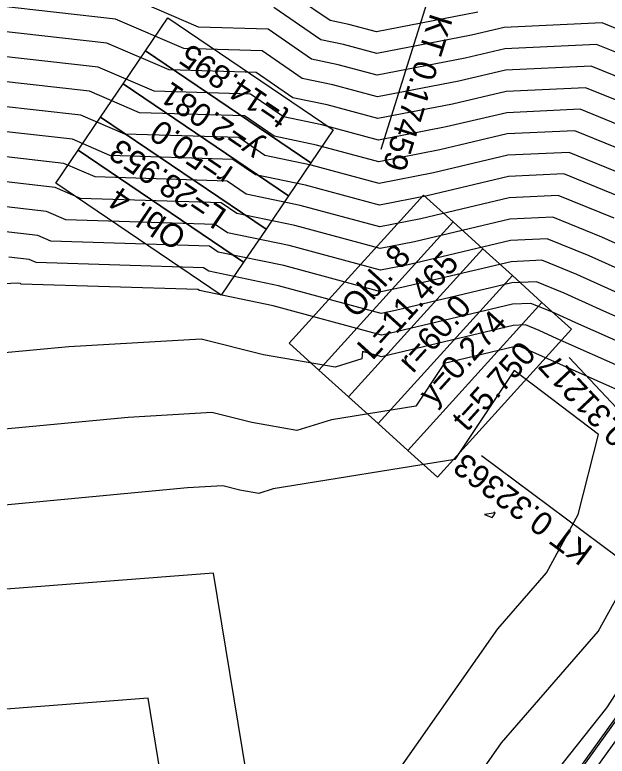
# Model space of a CAD drawing. Extents: x -549394 to -546608, y -1037055 to -1033629.
# Drawn here: x -547053.3 to -546964.3, y -1036015.8 to -1035904.5 of the extents above; entities that cross this region are included whole.
import ezdxf

# ---------------------------------------------------------------- set-up
doc = ezdxf.new("R2010")
doc.units = 0
for name, color, linetype in [('hlavni_vrst', 7, 'Continuous'), ('norm_vrst', 7, 'Continuous'), ('x_navrh_C31', 7, 'Continuous'), ('x_osa_C31', 7, 'Continuous'), ('x_popis_oblouky_C31', 7, 'Continuous')]:
    doc.layers.add(name, color=color, linetype=linetype)

msp = doc.modelspace()

# ---------------------------------------------------------------- linework, layer by layer
at = {"layer": 'hlavni_vrst'}
for p, q in [((-547007.32, -1035908.26), (-547014.4, -1035903.41)), ((-546965.11, -1035905.72), (-546979.83, -1035906.4)), ((-546948.31, -1035912.56), (-546965.11, -1035905.72)), ((-546979.83, -1035906.4), (-546984.72, -1035907.55)), ((-547003.92, -1035908.97), (-547007.32, -1035908.26)), ((-546984.72, -1035907.55), (-546998.92, -1035910.32)), ((-546998.92, -1035910.32), (-547003.92, -1035908.97)), ((-547042.05, -1035915.97), (-547063.4, -1035913.56)), ((-547034.56, -1035919.2), (-547042.05, -1035915.97)), ((-547018.79, -1035919.68), (-547034.56, -1035919.2)), ((-547014.34, -1035922.74), (-547018.79, -1035919.68)), ((-547007.99, -1035924.06), (-547014.34, -1035922.74)), ((-546979.34, -1035922.38), (-546989.48, -1035924.79)), ((-546969.22, -1035921.92), (-546979.34, -1035922.38)), ((-546957.68, -1035926.62), (-546969.22, -1035921.92)), ((-546998.65, -1035926.57), (-547007.99, -1035924.06)), ((-546989.48, -1035924.79), (-546998.65, -1035926.57)), ((-547048.55, -1035934.02), (-547056.82, -1035933.09)), ((-547045.65, -1035935.27), (-547048.55, -1035934.02)), ((-547023.18, -1035935.96), (-547045.65, -1035935.27)), ((-547021.36, -1035937.21), (-547023.18, -1035935.96)), ((-547012.07, -1035939.14), (-547021.36, -1035937.21)), ((-546978.84, -1035938.37), (-546994.24, -1035942.02)), ((-546973.33, -1035938.11), (-546978.84, -1035938.37)), ((-546967.05, -1035940.68), (-546973.33, -1035938.11)), ((-546998.39, -1035942.82), (-547012.07, -1035939.14)), ((-546958.93, -1035944.34), (-546967.05, -1035940.68)), ((-546994.24, -1035942.02), (-546998.39, -1035942.82)), ((-546978.35, -1035954.36), (-546988.8, -1035956.83)), ((-546977.44, -1035954.31), (-546978.35, -1035954.36)), ((-546976.41, -1035954.73), (-546977.44, -1035954.31)), ((-546975.08, -1035955.33), (-546976.41, -1035954.73)), ((-546959.74, -1035962.17), (-546975.08, -1035955.33)), ((-546988.8, -1035956.83), (-546993.09, -1035963.24)), ((-546993.09, -1035963.24), (-547005.75, -1035965.29)), ((-547036.25, -1035964.94), (-547063.11, -1035967.47)), ((-547023.68, -1035964.21), (-547036.25, -1035964.94)), ((-547017.72, -1035965.72), (-547023.68, -1035964.21)), ((-547010.93, -1035966.89), (-547017.72, -1035965.72)), ((-547005.75, -1035965.29), (-547010.93, -1035966.89)), ((-546965.68, -1035997.09), (-546956.18, -1035979.65)), ((-546980.23, -1036013.78), (-546965.68, -1035997.09)), ((-546988.48, -1036025.58), (-546980.23, -1036013.78))]:
    msp.add_line(p, q, dxfattribs=at)
at = {"layer": 'norm_vrst'}
for p, q in [((-547005.92, -1035905.37), (-547013.52, -1035900.15)), ((-547025.69, -1035906.34), (-547036.85, -1035901.52)), ((-547038.15, -1035905.14), (-547067.34, -1035901.85)), ((-546983.77, -1035904.11), (-546998.97, -1035907.07)), ((-547039.45, -1035908.75), (-547066.03, -1035905.75)), ((-547027.91, -1035909.55), (-547038.15, -1035905.14)), ((-547003.11, -1035905.95), (-547005.92, -1035905.37)), ((-546998.97, -1035907.07), (-547003.11, -1035905.95)), ((-547015.27, -1035906.66), (-547025.69, -1035906.34)), ((-547008.73, -1035911.16), (-547015.27, -1035906.66)), ((-547030.13, -1035912.77), (-547039.45, -1035908.75)), ((-546965.94, -1035908.96), (-546979.73, -1035909.59)), ((-546950.18, -1035915.37), (-546965.94, -1035908.96)), ((-547040.75, -1035912.36), (-547064.71, -1035909.66)), ((-547016.15, -1035909.92), (-547027.91, -1035909.55)), ((-547010.13, -1035914.05), (-547016.15, -1035909.92)), ((-546979.73, -1035909.59), (-546985.67, -1035911)), ((-547004.74, -1035911.99), (-547008.73, -1035911.16)), ((-546985.67, -1035911), (-546998.86, -1035913.57)), ((-547032.35, -1035915.98), (-547040.75, -1035912.36)), ((-547017.03, -1035913.17), (-547030.13, -1035912.77)), ((-546998.86, -1035913.57), (-547004.74, -1035911.99)), ((-546979.63, -1035912.79), (-546986.62, -1035914.45)), ((-546966.76, -1035912.2), (-546979.63, -1035912.79)), ((-546952.06, -1035918.19), (-546966.76, -1035912.2)), ((-547011.53, -1035916.95), (-547017.03, -1035913.17)), ((-547005.55, -1035915), (-547010.13, -1035914.05)), ((-546998.81, -1035916.82), (-547005.55, -1035915)), ((-546986.62, -1035914.45), (-546998.81, -1035916.82)), ((-547017.91, -1035916.43), (-547032.35, -1035915.98)), ((-546979.53, -1035915.99), (-546987.57, -1035917.89)), ((-546967.58, -1035915.44), (-546979.53, -1035915.99)), ((-546953.93, -1035921), (-546967.58, -1035915.44)), ((-547012.94, -1035919.84), (-547017.91, -1035916.43)), ((-547006.37, -1035918.02), (-547011.53, -1035916.95)), ((-547043.35, -1035919.58), (-547062.08, -1035917.47)), ((-546998.76, -1035920.07), (-547006.37, -1035918.02)), ((-546987.57, -1035917.89), (-546998.76, -1035920.07)), ((-546979.43, -1035919.19), (-546988.53, -1035921.34)), ((-546968.4, -1035918.68), (-546979.43, -1035919.19)), ((-546955.8, -1035923.81), (-546968.4, -1035918.68)), ((-547036.78, -1035922.41), (-547043.35, -1035919.58)), ((-547007.18, -1035921.04), (-547012.94, -1035919.84)), ((-547044.65, -1035923.19), (-547060.76, -1035921.37)), ((-546998.7, -1035923.32), (-547007.18, -1035921.04)), ((-546988.53, -1035921.34), (-546998.7, -1035923.32)), ((-547019.67, -1035922.94), (-547036.78, -1035922.41)), ((-547039, -1035925.63), (-547044.65, -1035923.19)), ((-547015.75, -1035925.63), (-547019.67, -1035922.94)), ((-547045.95, -1035926.8), (-547059.45, -1035925.28)), ((-547020.55, -1035926.2), (-547039, -1035925.63)), ((-547017.15, -1035928.53), (-547020.55, -1035926.2)), ((-547008.81, -1035927.07), (-547015.75, -1035925.63)), ((-546979.24, -1035925.58), (-546990.43, -1035928.23)), ((-546970.05, -1035925.16), (-546979.24, -1035925.58)), ((-546959.55, -1035929.43), (-546970.05, -1035925.16)), ((-547041.22, -1035928.84), (-547045.95, -1035926.8)), ((-546998.6, -1035929.82), (-547008.81, -1035927.07)), ((-546990.43, -1035928.23), (-546998.6, -1035929.82)), ((-546970.87, -1035928.39), (-546979.14, -1035928.78)), ((-546961.42, -1035932.24), (-546970.87, -1035928.39)), ((-547047.25, -1035930.41), (-547058.13, -1035929.18)), ((-547021.42, -1035929.45), (-547041.22, -1035928.84)), ((-547018.55, -1035931.42), (-547021.42, -1035929.45)), ((-547009.62, -1035930.09), (-547017.15, -1035928.53)), ((-546979.14, -1035928.78), (-546991.38, -1035931.68)), ((-547043.43, -1035932.06), (-547047.25, -1035930.41)), ((-546998.55, -1035933.07), (-547009.62, -1035930.09)), ((-547010.44, -1035933.11), (-547018.55, -1035931.42)), ((-546991.38, -1035931.68), (-546998.55, -1035933.07)), ((-546971.69, -1035931.63), (-546979.04, -1035931.98)), ((-546963.3, -1035935.05), (-546971.69, -1035931.63)), ((-547022.3, -1035932.71), (-547043.43, -1035932.06)), ((-547019.96, -1035934.32), (-547022.3, -1035932.71)), ((-546979.04, -1035931.98), (-546992.33, -1035935.12)), ((-546998.49, -1035936.32), (-547010.44, -1035933.11)), ((-547011.25, -1035936.12), (-547019.96, -1035934.32)), ((-546972.51, -1035934.87), (-546978.94, -1035935.17)), ((-546965.17, -1035937.87), (-546972.51, -1035934.87)), ((-546998.44, -1035939.57), (-547011.25, -1035936.12)), ((-546992.33, -1035935.12), (-546998.49, -1035936.32)), ((-546978.94, -1035935.17), (-546993.29, -1035938.57)), ((-547049.85, -1035937.63), (-547055.5, -1035936.99)), ((-547047.87, -1035938.49), (-547049.85, -1035937.63)), ((-546955.7, -1035942.14), (-546965.17, -1035937.87)), ((-547024.06, -1035939.22), (-547047.87, -1035938.49)), ((-547022.77, -1035940.11), (-547024.06, -1035939.22)), ((-546993.29, -1035938.57), (-546998.44, -1035939.57)), ((-547012.88, -1035942.16), (-547022.77, -1035940.11)), ((-547051.15, -1035941.24), (-547054.19, -1035940.9)), ((-547050.09, -1035941.7), (-547051.15, -1035941.24)), ((-547024.94, -1035942.48), (-547050.09, -1035941.7)), ((-546978.74, -1035941.57), (-546995.19, -1035945.46)), ((-546974.16, -1035941.35), (-546978.74, -1035941.57)), ((-546968.92, -1035943.49), (-546974.16, -1035941.35)), ((-547024.17, -1035943), (-547024.94, -1035942.48)), ((-546998.34, -1035946.08), (-547012.88, -1035942.16)), ((-547013.7, -1035945.18), (-547024.17, -1035943)), ((-546962.16, -1035946.54), (-546968.92, -1035943.49)), ((-547052.87, -1035944.81), (-547081.68, -1035946.16)), ((-547052.45, -1035944.85), (-547052.87, -1035944.81)), ((-547052.31, -1035944.92), (-547052.45, -1035944.85)), ((-547025.82, -1035945.73), (-547052.31, -1035944.92)), ((-546978.64, -1035944.76), (-546996.14, -1035948.91)), ((-546974.98, -1035944.59), (-546978.64, -1035944.76)), ((-546970.79, -1035946.3), (-546974.98, -1035944.59)), ((-547025.57, -1035945.9), (-547025.82, -1035945.73)), ((-547014.51, -1035948.19), (-547025.57, -1035945.9)), ((-546998.28, -1035949.33), (-547013.7, -1035945.18)), ((-546995.19, -1035945.46), (-546998.34, -1035946.08)), ((-546965.39, -1035948.74), (-546970.79, -1035946.3)), ((-546998.23, -1035952.58), (-547014.51, -1035948.19)), ((-546978.54, -1035947.96), (-546997.09, -1035952.36)), ((-546975.8, -1035947.83), (-546978.54, -1035947.96)), ((-546972.67, -1035949.11), (-546975.8, -1035947.83)), ((-546996.14, -1035948.91), (-546998.28, -1035949.33)), ((-546968.62, -1035950.94), (-546972.67, -1035949.11)), ((-546953.81, -1035953.9), (-546965.39, -1035948.74)), ((-546978.45, -1035951.16), (-546998.05, -1035955.8)), ((-546976.62, -1035951.07), (-546978.45, -1035951.16)), ((-546974.54, -1035951.92), (-546976.62, -1035951.07)), ((-546955.79, -1035956.66), (-546968.62, -1035950.94)), ((-546997.09, -1035952.36), (-546998.23, -1035952.58)), ((-546971.85, -1035953.14), (-546974.54, -1035951.92)), ((-547025.33, -1035953.18), (-547045.17, -1035954.34)), ((-547015.93, -1035955.56), (-547025.33, -1035953.18)), ((-546957.77, -1035959.42), (-546971.85, -1035953.14)), ((-547045.17, -1035954.34), (-547057.43, -1035955.49)), ((-547001.1, -1035955.04), (-547001.17, -1035956.17)), ((-546998.18, -1035955.83), (-547001.1, -1035955.04)), ((-547005.2, -1035957.42), (-547015.93, -1035955.56)), ((-547001.17, -1035956.17), (-547005.2, -1035957.42)), ((-546998.05, -1035955.8), (-546998.18, -1035955.83)), ((-546978.31, -1035957.92), (-546987.24, -1035971.27)), ((-546965.65, -1035967.53), (-546978.31, -1035957.92)), ((-546968.7, -1035979.52), (-546965.65, -1035967.53)), ((-546987.24, -1035971.27), (-547014.47, -1035975.69)), ((-547027.34, -1035975.54), (-547068.8, -1035979.44)), ((-547022.03, -1035975.23), (-547027.34, -1035975.54)), ((-547019.52, -1035975.87), (-547022.03, -1035975.23)), ((-547016.65, -1035976.36), (-547019.52, -1035975.87)), ((-547014.47, -1035975.69), (-547016.65, -1035976.36)), ((-546981.4, -1035979.3), (-546982.75, -1035979.52)), ((-546982.75, -1035979.52), (-546981.61, -1035979.95)), ((-546981.61, -1035979.95), (-546981.33, -1035979.55)), ((-546981.31, -1035979.17), (-546981.4, -1035979.3)), ((-546981.33, -1035979.55), (-546981.26, -1035979.47)), ((-546981.18, -1035979.26), (-546981.31, -1035979.17)), ((-546981.26, -1035979.47), (-546981.21, -1035979.38)), ((-546981.21, -1035979.38), (-546981.18, -1035979.26)), ((-546973.47, -1035988.28), (-546968.7, -1035979.52)), ((-547023.47, -1035988.34), (-547072.1, -1035992.07)), ((-547016.71, -1036029.45), (-547023.47, -1035988.34)), ((-546980.78, -1035996.67), (-546973.47, -1035988.28)), ((-547003.52, -1036029.16), (-546980.78, -1035996.67)), ((-546964.39, -1036008.54), (-546961.24, -1036003.64)), ((-547033.27, -1036007.09), (-547059.49, -1036009.1)), ((-547029.62, -1036029.26), (-547033.27, -1036007.09)), ((-546972.34, -1036018.53), (-546964.39, -1036008.54))]:
    msp.add_line(p, q, dxfattribs=at)
at = {"layer": 'x_navrh_C31'}
msp.add_line((-547002.86, -1036065.86), (-546951.46, -1035994.4), dxfattribs=at)
msp.add_lwpolyline([(-546997.24, -1036057.61), (-546951.66, -1035994.26)], dxfattribs=at)
for radius in [38.25, 37.46]:
    msp.add_arc((-546980, -1035928.75), radius, 37.7126, 73.4173, dxfattribs=at)
at = {"layer": 'x_osa_C31'}
msp.add_lwpolyline([(-547007, -1036074.62), (-546946.36, -1035990.32), (-546926.05, -1035971.84), (-546925.92, -1035933.3), (-546935.95, -1035920.32)], dxfattribs=at)
at = {"layer": 'x_popis_oblouky_C31'}
for points in [[(-546985.95, -1035885.24), (-546998.35, -1035924.72)], [(-546941.7, -1035986.08), (-546970.07, -1035955.96)], [(-546950.04, -1035995.43), (-546983.22, -1035970.71)]]:
    msp.add_lwpolyline(points, dxfattribs=at)
for points in [[(-547008.84, -1035926.73), (-547033.68, -1035909.91), (-547030.32, -1035904.94), (-547005.47, -1035921.76)], [(-547012.2, -1035931.7), (-547037.04, -1035914.88), (-547033.68, -1035909.91), (-547008.84, -1035926.73)], [(-547015.56, -1035936.66), (-547040.41, -1035919.85), (-547037.04, -1035914.88), (-547012.2, -1035931.7)], [(-547018.93, -1035941.63), (-547043.77, -1035924.82), (-547040.41, -1035919.85), (-547015.56, -1035936.66)], [(-547022.29, -1035946.6), (-547047.13, -1035929.78), (-547043.77, -1035924.82), (-547018.93, -1035941.63)], [(-547012.07, -1035953.8), (-546991.92, -1035931.57), (-546987.48, -1035935.6), (-547007.62, -1035957.83)], [(-547007.62, -1035957.83), (-546987.48, -1035935.6), (-546983.03, -1035939.62), (-547003.17, -1035961.86)], [(-547003.17, -1035961.86), (-546983.03, -1035939.62), (-546978.58, -1035943.65), (-546998.73, -1035965.88)], [(-546998.73, -1035965.88), (-546978.58, -1035943.65), (-546974.14, -1035947.68), (-546994.28, -1035969.91)], [(-546994.28, -1035969.91), (-546974.14, -1035947.68), (-546969.69, -1035951.71), (-546989.83, -1035973.94)]]:
    msp.add_lwpolyline(points, close=True, dxfattribs=at)

# ---------------------------------------------------------------- texts
for s, rotation, p in [('KT 0.17459', 252.5712, (-546990.84, -1035904.14)), ('t=14.895', 145.9269, (-547011.77, -1035918.95)), ('y=2.081', 145.9269, (-547015.91, -1035923.82)), ('r=50.0', 145.9269, (-547020.28, -1035927.57)), ('L=28.953', 145.9269, (-547021.23, -1035933.97)), ('Obl. 4', 145.9269, (-547027.25, -1035937.14)), ('Obl. 8', 47.842, (-547002, -1035950.22)), ('L=11.465', 47.842, (-546999.6, -1035956.51)), ('r=60.0', 47.842, (-546993.51, -1035958.46)), ('y=0.274', 47.842, (-546990.41, -1035963.32)), ('t=5.750', 47.842, (-546985.39, -1035967.24)), ('TK 0.31217', 133.2795, (-546955.77, -1035972.6)), ('KT 0.32363', 143.3215, (-546966.27, -1035984.58))]:
    msp.add_text(s, height=3.5, rotation=rotation, dxfattribs=at).set_placement(p)

doc.saveas('drawing.dxf')
